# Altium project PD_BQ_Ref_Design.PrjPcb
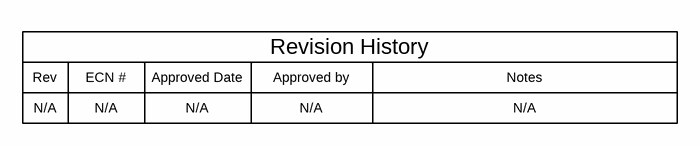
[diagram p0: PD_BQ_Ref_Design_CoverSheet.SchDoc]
TID: N/A; TechSupport: http://www.ti.com/support; SCH_Rev: A1; PRJ_Title: PD Reference Design; PRJ_Number: BMS046_; PRJ_Engineer: Hari Patel; PRJ_Customer: Public Release; PCB_Rev: A1; PCB_Layout: Outsource; CopyrightYear: 2018
7 sheets, 125 parts. Net scope: global (net labels, ports and power ports of the same name join across sheets).
Board file: PD_BQ_Ref_Design_PCB.PcbDoc
Sheets:
  PD_BQ_Ref_Design_BlankSheet.SchDoc
  PD_BQ_Ref_Design_CoverSheet.SchDoc
  PD_BQ_Ref_Design_Hardware.SchDoc
  TPS25750D.SchDoc
  BQ25792.SchDoc
  Type_C_Port.SchDoc
  Power_5V_3.3V.SchDoc

## Sheet PD_BQ_Ref_Design_BlankSheet.SchDoc
size 431 x 279 mm; Date: Not shown in title block; ApprovedBy: Not shown in title block; CheckedBy: Not shown in title block; Author: Not shown in title block; CompanyName: Not shown in title block; Engineer: Not shown in title block; Organization: Not shown in title block; Address1: Not shown in title block; Address2: Not shown in title block; Address3: Not shown in title block; Address4: Not shown in title block; DocumentNumber: 2; Revision: Use project parameter SCH_Rev; SheetNumber: 2; SheetTotal: 3; PageSetup: Record=PageOptions¦CenterHorizontal=True¦CenterVertical=True¦PrintScale=1.00¦XCorrection=1.00¦YCorrection=1.00¦PrintKind=0¦BorderSize=5000000¦LeftOffset=0¦BottomOffset=0¦Orientation=2¦PaperLength=1000¦PaperWidth=1000¦Scale=100¦PaperSource=15¦PrintQuality=600¦MediaType=1¦DitherType=10¦PaperKind=Letter¦PrintScaleMode=1

## Sheet PD_BQ_Ref_Design_CoverSheet.SchDoc
size 431 x 279 mm; Date: Not shown in title block; ApprovedBy: Not shown in title block; CheckedBy: Not shown in title block; Author: Not shown in title block; CompanyName: Not shown in title block; Engineer: Not shown in title block; Organization: Not shown in title block; Address1: Not shown in title block; Address2: Not shown in title block; Address3: Not shown in title block; Address4: Not shown in title block; DocumentNumber: 1; Revision: Use project parameter SCH_Rev; SheetNumber: 1; SheetTotal: 3; PageSetup: Record=PageOptions¦CenterHorizontal=True¦CenterVertical=True¦PrintScale=1.00¦XCorrection=1.00¦YCorrection=1.00¦PrintKind=0¦BorderSize=5000000¦LeftOffset=0¦BottomOffset=0¦Orientation=2¦PaperLength=1000¦PaperWidth=1000¦Scale=100¦PaperSource=15¦PrintQuality=600¦MediaType=1¦DitherType=10¦PaperKind=Letter¦PrintScaleMode=1

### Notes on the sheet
- Rev
- N/A
- ECN #
- Approved Date
- Approved by
- Revision History
- Notes

## Sheet PD_BQ_Ref_Design_Hardware.SchDoc
size 431 x 279 mm; Date: Not shown in title block; ApprovedBy: Not shown in title block; CheckedBy: Not shown in title block; Author: Not shown in title block; CompanyName: Not shown in title block; Engineer: Not shown in title block; Organization: Not shown in title block; Address1: Not shown in title block; Address2: Not shown in title block; Address3: Not shown in title block; Address4: Not shown in title block; DocumentNumber: 1; Revision: Use project parameter SCH_Rev; SheetNumber: 1; SheetTotal: 1; PageSetup: Record=PageOptions¦CenterHorizontal=True¦CenterVertical=True¦PrintScale=1.00¦XCorrection=1.00¦YCorrection=1.00¦PrintKind=0¦BorderSize=5000000¦LeftOffset=0¦BottomOffset=0¦Orientation=2¦PaperLength=1000¦PaperWidth=1000¦Scale=100¦PaperSource=15¦PrintQuality=600¦MediaType=1¦DitherType=10¦PaperKind=Letter¦PrintScaleMode=1
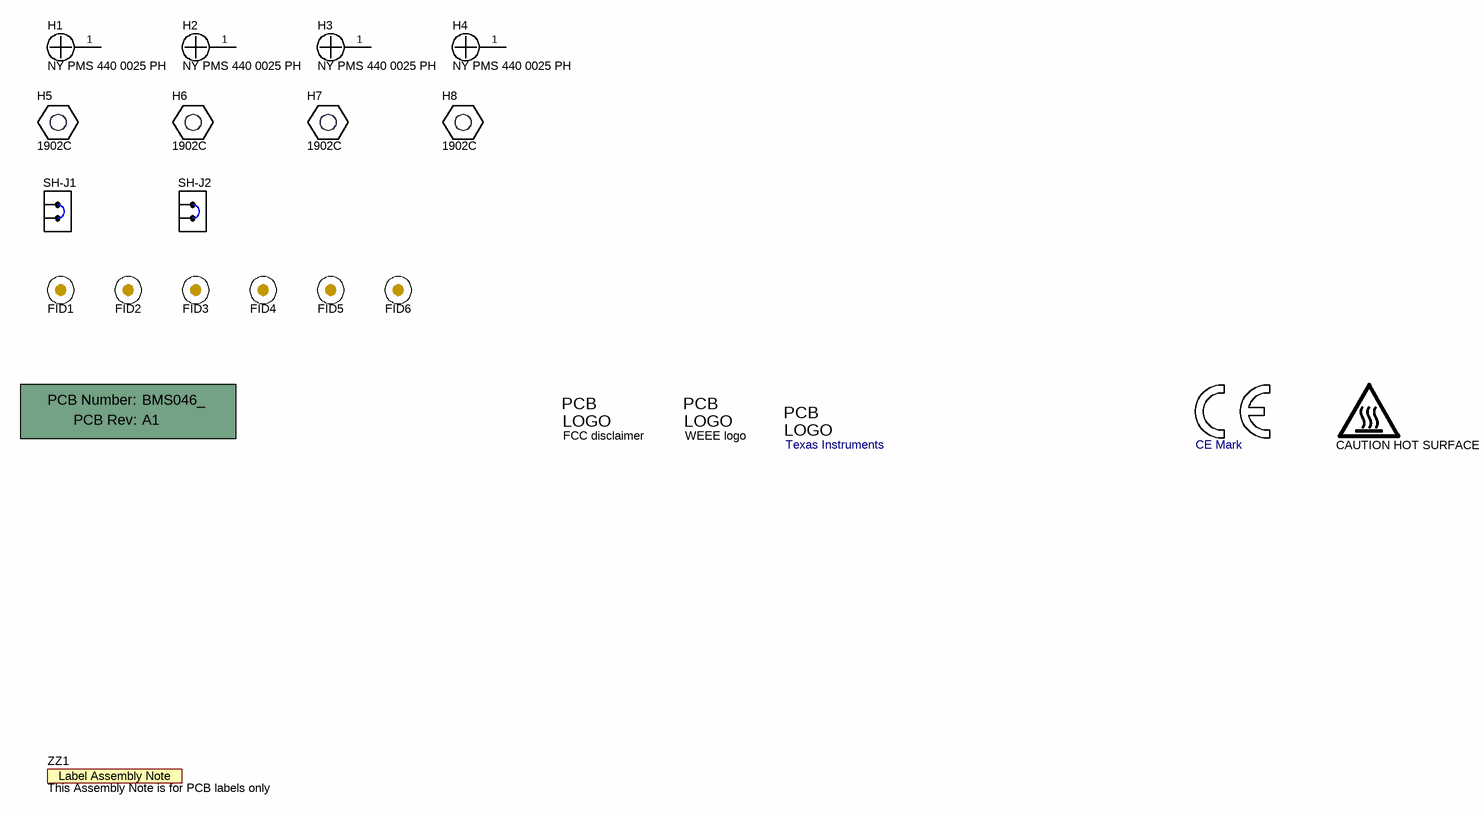
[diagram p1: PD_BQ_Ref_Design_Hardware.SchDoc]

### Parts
!PCB1  Printed Circuit Board  (value not drawn)  (mechanical)
FID1  Fiducial  [Fiducial10-20]  (value not drawn)
FID2  Fiducial  [Fiducial10-20]  (value not drawn)
FID3  Fiducial  [Fiducial10-20]  (value not drawn)
FID4  Fiducial  [Fiducial10-20]  (value not drawn)
FID5  Fiducial  [Fiducial10-20]  (value not drawn)
FID6  Fiducial  [Fiducial10-20]  (value not drawn)
H1  NY PMS 440 0025 PH  [NY PMS 440 0025 PH]
H2  NY PMS 440 0025 PH  [NY PMS 440 0025 PH]
H3  NY PMS 440 0025 PH  [NY PMS 440 0025 PH]
H4  NY PMS 440 0025 PH  [NY PMS 440 0025 PH]
H5  1902C  [Keystone_1902C]
H6  1902C  [Keystone_1902C]
H7  1902C  [Keystone_1902C]
H8  1902C  [Keystone_1902C]
Logo1  CE Mark  [CE_Mark_5mm]  (no BOM)
Logo2  Texas Instruments  [TI_Horizontal_Overlay_Small]  (no BOM)
Logo3  FCC disclaimer  [FCC_disclaimer]  (no BOM)
Logo4  WEEE logo  [WEEE_Minimum]  (no BOM)
LOGO5  CAUTION HOT SURFACE  [IEC_HotSurface_Small]  (no BOM)
SH-J1  SNT-100-BK-G  [SNT-100-BK-G]  (value not drawn)
SH-J2  SNT-100-BK-G  [SNT-100-BK-G]  (value not drawn)
ZZ1  This Assembly Note is for PCB labels only  [AssemblyNoteLabel]  (no BOM)

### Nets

Not connected (* = marked no-connect by the designer): H1 1; H2 1; H3 1; H4 1

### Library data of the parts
!PCB1 = CMP-0003618-2: Manufacturer: Any; PartNumber: BMS046_
FID1-FID6 = CMP-0077181-1: Fiducial mark.  There is nothing to buy or mount.
H1-H4 = CMP-0003617-1: Machine Screw, Round, #4-40 x 1/4, Nylon, Philips panhead; Manufacturer: B&F Fastener Supply; CompType: Hardware
H5-H8 = CMP-0003610-1: Standoff, Hex, 0.5"L #4-40 Nylon; Manufacturer: Keystone; CompType: Hardware
Logo1 = CMP-0074844-1: SymbolCreator: a0412235
Logo2 = CMP-0074838-1: Texas Instrument Corporate Signature; SymbolCreator: a0412235; Lib Reference: TI_Logo
Logo3 = CMP-0074847-1: FCC_disclaimer; Library Reference: Logo
Logo4 = CMP-0074769-1
LOGO5 = CMP-0074837-1: IEC 61010-1 Hot Surface Warning; SymbolCreator: a0412235
SH-J1 SH-J2 = CMP-0003623-1: Shunt, 100mil, Gold plated, Black; Alternate PartNumber: 969102-0000-DA; Manufacturer: Samtec; Alternate Manufacturer: 3M; Value: 1x2; Note: You can "mate" this to a header by matching the designator.  i.e. use SH-J3 for header J3
ZZ1 = CMP-0003616-3

## Sheet TPS25750D.SchDoc
size A2; Date: Not shown in title block; ApprovedBy: Not shown in title block; CheckedBy: Not shown in title block; Author: Not shown in title block; CompanyName: Not shown in title block; Engineer: Not shown in title block; Organization: Not shown in title block; Address1: Not shown in title block; Address2: Not shown in title block; Address3: Not shown in title block; Address4: Not shown in title block; DocumentNumber: 2; Revision: Use project parameter SCH_Rev; SheetNumber: 2; SheetTotal: 3; PageSetup: Record=PageOptions¦CenterHorizontal=True¦CenterVertical=True¦PrintScale=1.00¦XCorrection=1.00¦YCorrection=1.00¦PrintKind=0¦BorderSize=5000000¦LeftOffset=0¦BottomOffset=0¦Orientation=2¦PaperLength=1000¦PaperWidth=1000¦Scale=100¦PaperSource=15¦PrintQuality=600¦MediaType=1¦DitherType=10¦PaperKind=Letter¦PrintScaleMode=1
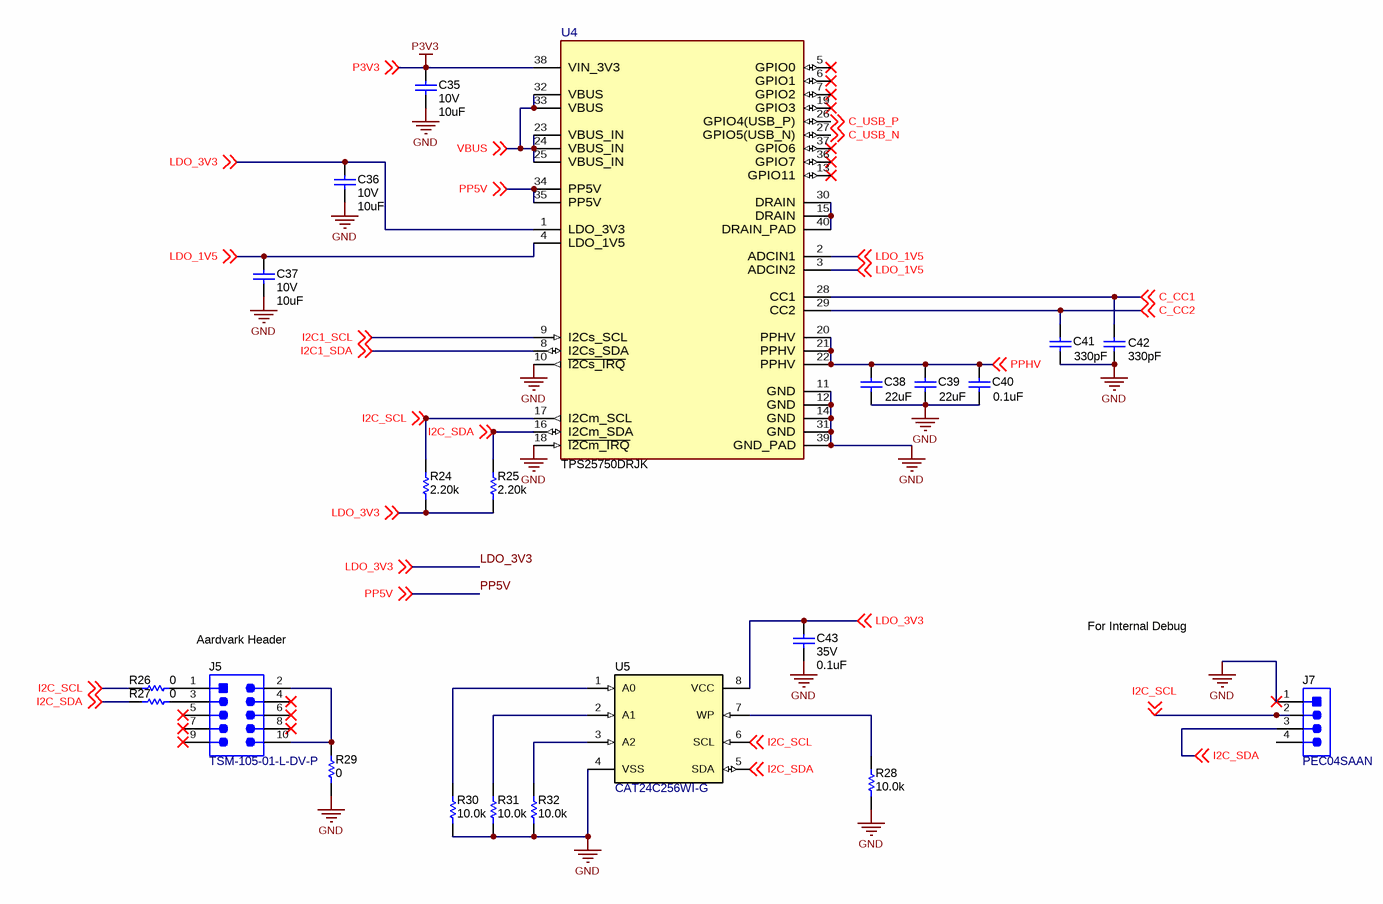
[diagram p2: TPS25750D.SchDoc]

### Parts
C35  VDC_V: 10V  ValueDisplayed: 10uF  [0402_070]  (hidden comment: CL05A106MP5NUNC)
C36  VDC_V: 10V  ValueDisplayed: 10uF  [0402_070]  (hidden comment: CL05A106MP5NUNC)
C37  VDC_V: 10V  ValueDisplayed: 10uF  [0402_070]  (hidden comment: CL05A106MP5NUNC)
C38  ValueDisplayed: 22uF  [0805_HV]  (hidden comment: C2012X5R1V226M125AC)
C39  ValueDisplayed: 22uF  [0805_HV]  (hidden comment: C2012X5R1V226M125AC)
C40  ValueDisplayed: 0.1uF  [0402]  (hidden comment: GMK105BJ104KV-F)
C41  ValueDisplayed: 330pF  [0201_033]  (hidden comment: GRM033R71H331KA12D)
C42  ValueDisplayed: 330pF  [0201_033]  (hidden comment: GRM033R71H331KA12D)
C43  VDC_V: 35V  ValueDisplayed: 0.1uF  [0402]  (hidden comment: GMK105BJ104KV-F)
J5  TSM-105-01-L-DV-P  [Samtec_TSM-105-01-x-DV]
J7  PEC04SAAN  [SULLINS_PEC04SAAN]
R24  ValueDisplayed: 2.20k  [0201]  (hidden comment: CRCW02012K20FKED)
R25  ValueDisplayed: 2.20k  [0201]  (hidden comment: CRCW02012K20FKED)
R26  ValueDisplayed: 0  [0201]  (hidden comment: CRCW02010000Z0ED)
R27  ValueDisplayed: 0  [0201]  (hidden comment: CRCW02010000Z0ED)
R28  ValueDisplayed: 10.0k  [0201]  (hidden comment: CRCW020110K0FKED)
R29  ValueDisplayed: 0  [0201]  (hidden comment: CRCW02010000Z0ED)
R30  ValueDisplayed: 10.0k  [0201]  (hidden comment: CRCW020110K0FKED)
R31  ValueDisplayed: 10.0k  [0201]  (hidden comment: CRCW020110K0FKED)
R32  ValueDisplayed: 10.0k  [0201]  (hidden comment: CRCW020110K0FKED)
U4  TPS25750DRJK  [RJK0038B-C01-MFG]
U5  CAT24C256WI-G  [SOIC-8]

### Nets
GND: C35.2 C36.2 C37.2 C38.2 C39.2 C40.2 C41.2 C42.2 C43.2 J7.1 R28.1 R29.1 R30.1 R31.1 R32.1 U4.10(~{I2Cs_IRQ}) U4.11(GND) U4.12(GND) U4.14(GND) U4.18(~{I2Cm_IRQ}) U4.31(GND) U4.39(GND_PAD) U5.4(VSS)
P3V3: C35.1 U4.38(VIN_3V3) ; off-sheet P3V3
C_CC1: C42.1 U4.28(CC1) ; off-sheet C_CC1
C_CC2: C41.1 U4.29(CC2) ; off-sheet C_CC2
C_USB_N: U4.27(GPIO5(USB_N)) ; off-sheet C_USB_N
C_USB_P: U4.26(GPIO4(USB_P)) ; off-sheet C_USB_P
I2C1_SCL: U4.9(I2Cs_SCL) ; off-sheet I2C1_SCL
I2C1_SDA: U4.8(I2Cs_SDA) ; off-sheet I2C1_SDA
I2C_SCL: J7.2 R24.2 R26.1 U4.17(I2Cm_SCL) U5.6(SCL) ; off-sheet I2C_SCL
I2C_SDA: J7.3 R25.2 R27.1 U4.16(I2Cm_SDA) U5.5(SDA) ; off-sheet I2C_SDA
LDO_1V5: C37.1 U4.2(ADCIN1) U4.3(ADCIN2) U4.4(LDO_1V5) ; off-sheet LDO_1V5
LDO_3V3: C36.1 C43.1 R24.1 R25.1 U4.1(LDO_3V3) U5.8(VCC) ; off-sheet LDO_3V3
PP5V: U4.34(PP5V) U4.35(PP5V) ; off-sheet PP5V
PPHV: C38.1 C39.1 C40.1 U4.20(PPHV) U4.21(PPHV) U4.22(PPHV) ; off-sheet PPHV
VBUS: U4.23(VBUS_IN) U4.24(VBUS_IN) U4.25(VBUS_IN) U4.32(VBUS) U4.33(VBUS) ; off-sheet VBUS
NetJ5_1: J5.1 R26.2
NetJ5_2: J5.2 J5.10 R29.2
NetJ5_3: J5.3 R27.2
NetR28_2: R28.2 U5.7(WP)
NetR30_2: R30.2 U5.1(A0)
NetR31_2: R31.2 U5.2(A1)
NetR32_2: R32.2 U5.3(A2)
NetU4_15: U4.15(DRAIN) U4.30(DRAIN) U4.40(DRAIN_PAD)

Not connected (* = marked no-connect by the designer): J5 4* 5* 6* 7* 8* 9*; J7 4; U4 5(GPIO0)* 6(GPIO1)* 7(GPIO2)* 13(GPIO11)* 19(GPIO3)* 36(GPIO7)* 37(GPIO6)*

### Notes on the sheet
- Aardvark Header
- For Internal Debug

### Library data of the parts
C35-C37 = CMP-0006339-4: CAP, CERM, 10 uF, 10 V, +/- 20%, X5R, 0402; Manufacturer: Samsung Electro-Mechanics; TaMin_C: -55°C; Polarized: N; SizeAreaWB_mm2: 3; Value1: Unknown; U/M: EA; Value: 10uF; TaMax_C: 85°C; SizeZ_mm: 0.6; SizeX_mm: 1; SizeY_mm: 0.5; Cap_Case: 0402; Cap_F: 10µF; AEC Category: Q200
C38 C39 = CMP-0007844-2: CAP, CERM, 22 uF, 35 V, +/- 20%, X5R, 0805; Manufacturer: TDK; TaMin_C: -55°C; ESR_ohm: 2.05m; Polarized: N; SizeAreaWB_mm2: 6.75; Value1: 0.00205 ohm; U/M: EA; Value: 22uF; TaMax_C: 85°C; SizeZ_mm: 1.45; SizeX_mm: 2; SizeY_mm: 1.25; Cap_Case: 0805; Value2: 35V; SizeArea_mm2: 2.5; Cap_F: 22µF; IRMS_A: 4.55587A; AEC Category: Q200
C40 = CMP-0006370-2: CAP, CERM, 0.1 uF, 35 V, +/- 10%, X5R, 0402; Manufacturer: Taiyo Yuden; TaMin_C: -55°C; Polarized: N; SizeAreaWB_mm2: 3; Value1: Unknown; U/M: EA; Value: 0.1uF; TaMax_C: 85°C; SizeZ_mm: 0.6; SizeX_mm: 1; SizeY_mm: 0.5; Value2: 35V; Cap_F: 100nF; AEC Category: Q200
C41 C42 = CMP-0009779-2: CAP, CERM, 330 pF, 50 V, +/- 10%, X7R, 0201; Manufacturer: MuRata; TaMin_C: -55°C; Polarized: N; SizeAreaWB_mm2: 2.08; Value1: Unknown; U/M: EA; Value: 330pF; TaMax_C: 125°C; SizeZ_mm: 0.33; SizeX_mm: 0.6; SizeY_mm: 0.3; Cap_Case: 0201; Value2: 50V; SizeArea_mm2: 0.18; AEC Category: Q200
C43 = CMP-0006370-2: CAP, CERM, 0.1 uF, 35 V, +/- 10%, X5R, 0402; Manufacturer: Taiyo Yuden; TaMin_C: -55°C; Polarized: N; SizeAreaWB_mm2: 3; Value1: Unknown; U/M: EA; Value: 0.1uF; TaMax_C: 85°C; SizeZ_mm: 0.6; SizeX_mm: 1; SizeY_mm: 0.5; Cap_F: 100nF; AEC Category: Q200
J5 = CMP-0055598-2: Header, 2.54mm, 5x2, Gold, SMT; Manufacturer: Samtec; Current_A: 5.4A; Green_Lifecycle: Active; Shrouded: N; Gender: Male; Cert_CSA: Y; Green_REACh: Passed; Voltage_V: 475V; Row_Count: 2; RowSpacing_mm: 2.54
J7 = CMP-0054562-1: Header, 100mil, 4x1, Tin, TH; Manufacturer: Sullins Connector Solutions; CNHeader: TRUE; Current_A: 3A; Green_Lifecycle: Not Set; Shrouded: N; Gender: Male; Green_REACh: Incomplete; Voltage_V: 1.8kV; Row_Count: 1; Pitch_mm: 2.54; CT: FALSE; Cert_UL: Y
R24 R25 = CMP-0027272-3: RES, 2.20 k, 1%, 0.05 W, 0201; Manufacturer: Vishay-Dale; Power_W: 50mW; TempCo: 100 ppm/C; Value_Code: 2k20; Value: 2.20k; Res_ohm: 2.2k; SizeX_mm: 0.6; SizeY_mm: 0.3; SizeZ_mm: 0.26; Value2: 0.05W; SizeArea_mm2: 0.18; AEC Qualified: N; VDC_V: 30V; AEC Category: Q200
R26 R27 R29 = CMP-0027008-4: RES, 0, 5%, 0.05 W, 0201; Manufacturer: Vishay-Dale; Power_W: 50mW; TempCo: ppm/C; Value_Code: 0000; Value: 0; EIA_Code: E24; SizeX_mm: 0.6; SizeY_mm: 0.3; SizeZ_mm: 0.26; Value2: 0.05W; SizeArea_mm2: 0.18; AEC Qualified: N; AEC Category: Q200
R28 R30-R32 = CMP-0027262-3: RES, 10.0 k, 1%, 0.05 W, 0201; Manufacturer: Vishay-Dale; Power_W: 50mW; TempCo: 100 ppm/C; Value_Code: 10k0; Value: 10.0k; EIA_Code: E96; Res_ohm: 10k; SizeX_mm: 0.6; SizeY_mm: 0.3; SizeZ_mm: 0.26; Value2: 0.05W; SizeArea_mm2: 0.18; AEC Qualified: N; VDC_V: 30V; AEC Category: Q200
U4 = CMP-0090338-5: USB Type-C and USB PD Controller with Integrated Power Switches Optimized for Power Applications; Manufacturer: Texas Instruments; CompType: IC; Usb Standard: USB 3.0; AEC Category: Q200; SizeZ_mm: 0.8mm; Standoff Height: 0mm; AEC Qualified: No; Max Supply Voltage: 22V; TaMax_C: +105°C; Min Supply Voltage: 3V; TaMin_C: -40°C; TJmax_C: +175°C; Number Of Ports: 1
U5 = CMP-0005314-2: 256 kb I2C CMOS Serial EEPROM, SOIC-8; Manufacturer: ON Semiconductor; SizeAreaWB_mm2: 55.131; SizeZ_mm: 1.75; SizeX_mm: 5.99; SizeY_mm: 4.9; SizeArea_mm2: 29.351

## Sheet BQ25792.SchDoc
size A2; Date: Not shown in title block; ApprovedBy: Not shown in title block; CheckedBy: Not shown in title block; Author: Not shown in title block; CompanyName: Not shown in title block; Engineer: Not shown in title block; Organization: Not shown in title block; Address1: Not shown in title block; Address2: Not shown in title block; Address3: Not shown in title block; Address4: Not shown in title block; DocumentNumber: 2; Revision: Use project parameter SCH_Rev; SheetNumber: 2; SheetTotal: 3; PageSetup: Record=PageOptions¦CenterHorizontal=True¦CenterVertical=True¦PrintScale=1.00¦XCorrection=1.00¦YCorrection=1.00¦PrintKind=0¦BorderSize=5000000¦LeftOffset=0¦BottomOffset=0¦Orientation=2¦PaperLength=1000¦PaperWidth=1000¦Scale=100¦PaperSource=15¦PrintQuality=600¦MediaType=1¦DitherType=10¦PaperKind=Letter¦PrintScaleMode=1
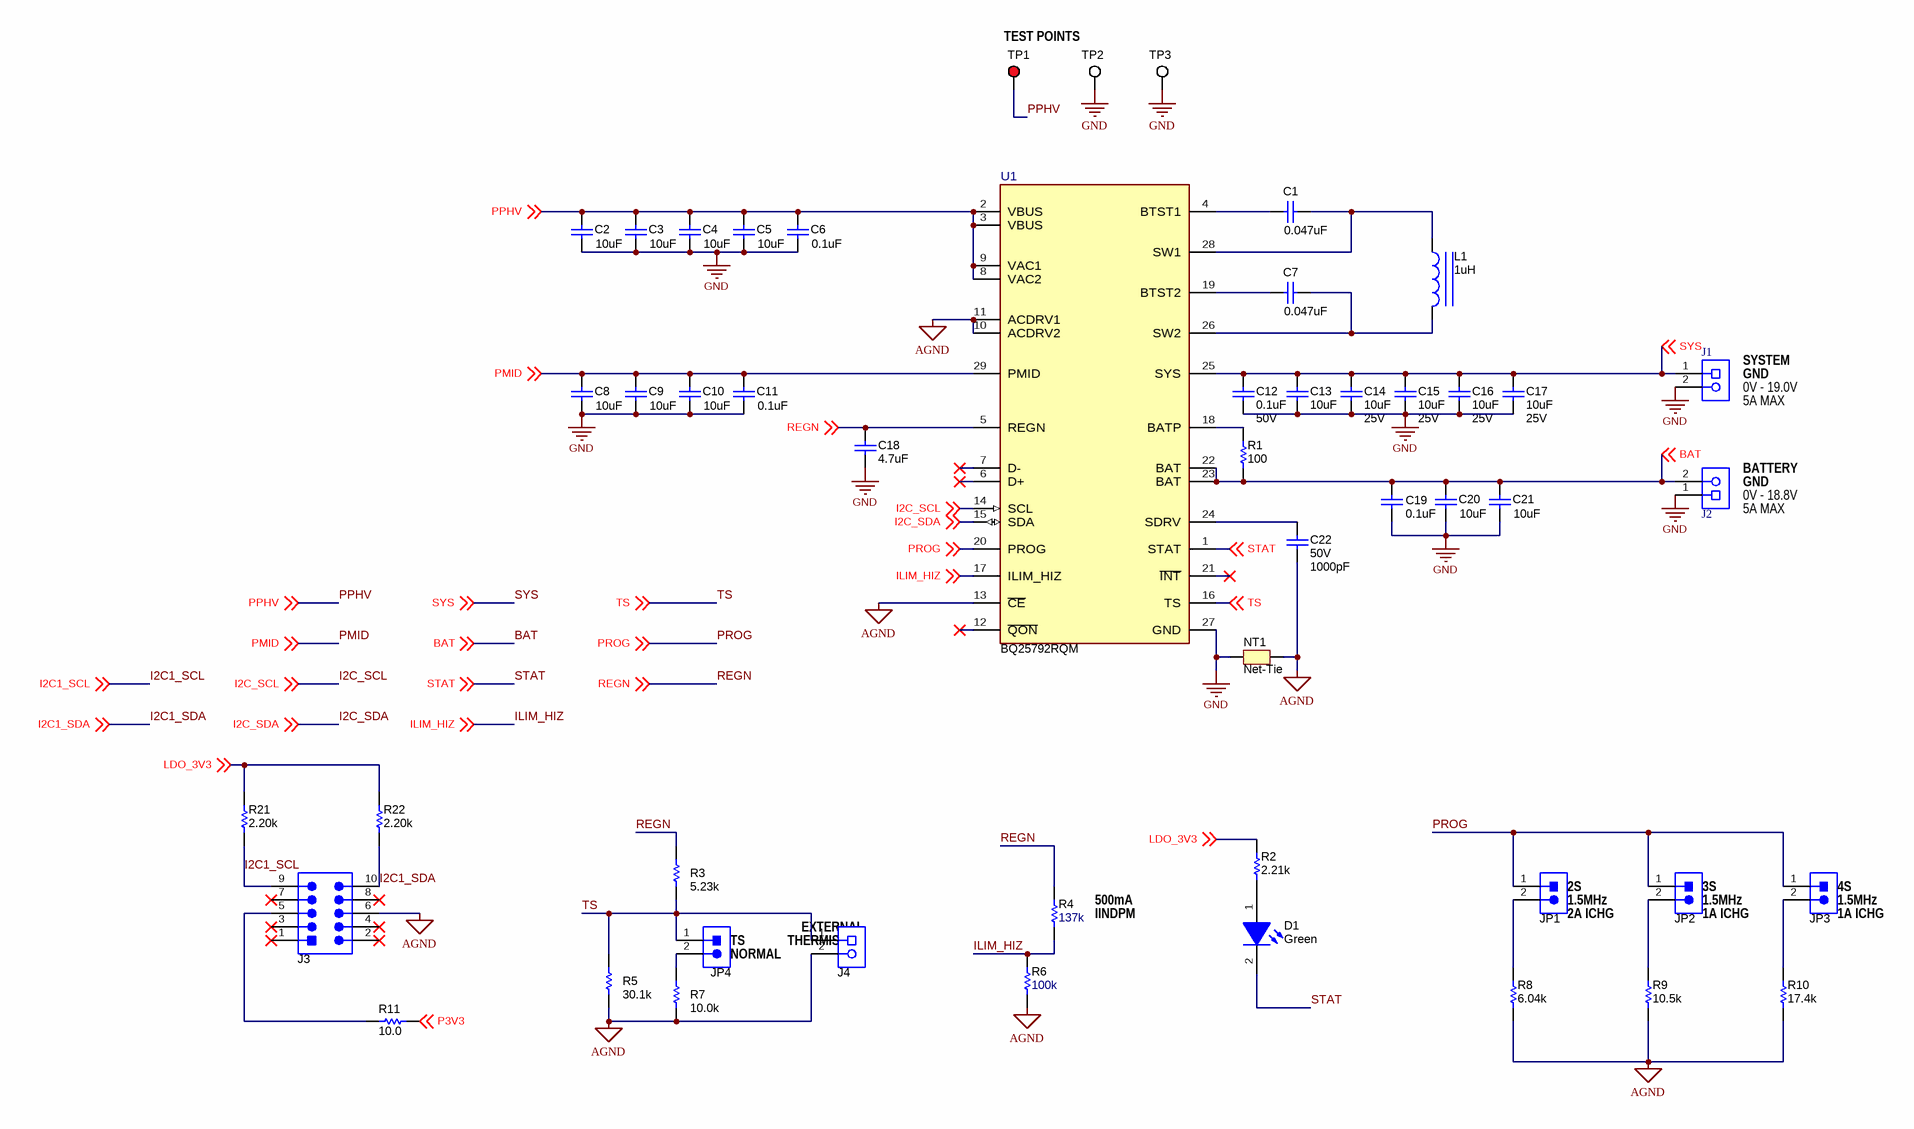
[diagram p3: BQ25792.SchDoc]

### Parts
C1  ValueDisplayed: 0.047uF  [0402]  (hidden comment: GRM155R71E473KA88D)
C2  ValueDisplayed: 10uF  [0603]  (hidden comment: GRT188R61E106ME13D)
C3  ValueDisplayed: 10uF  [0603]  (hidden comment: GRT188R61E106ME13D)
C4  ValueDisplayed: 10uF  [0603]  (hidden comment: GRT188R61E106ME13D)
C5  ValueDisplayed: 10uF  [0603]  (hidden comment: GRT188R61E106ME13D)
C6  ValueDisplayed: 0.1uF  [0402]  (hidden comment: C1005X7R1H104K050BE)
C7  ValueDisplayed: 0.047uF  [0402]  (hidden comment: GRM155R71E473KA88D)
C8  ValueDisplayed: 10uF  [0603]  (hidden comment: GRT188R61E106ME13D)
C9  ValueDisplayed: 10uF  [0603]  (hidden comment: GRT188R61E106ME13D)
C10  ValueDisplayed: 10uF  [0603]  (hidden comment: GRT188R61E106ME13D)
C11  ValueDisplayed: 0.1uF  [0402]  (hidden comment: C1005X7R1H104K050BE)
C12  ValueDisplayed: 0.1uF  VDC_V: 50V  [0402]  (hidden comment: C1005X7R1H104K050BE)
C13  ValueDisplayed: 10uF  [0805_HV]  (hidden comment: C2012X5R1E106K125AB)
C14  ValueDisplayed: 10uF  VDC_V: 25V  [0805_HV]  (hidden comment: C2012X5R1E106K125AB)
C15  ValueDisplayed: 10uF  VDC_V: 25V  [0805_HV]  (hidden comment: C2012X5R1E106K125AB)
C16  ValueDisplayed: 10uF  VDC_V: 25V  [0805_HV]  (hidden comment: C2012X5R1E106K125AB)
C17  ValueDisplayed: 10uF  VDC_V: 25V  [0805_HV]  (hidden comment: C2012X5R1E106K125AB)
C18  ValueDisplayed: 4.7uF  [0603]  (hidden comment: GRM188R61C475KAAJ)
C19  ValueDisplayed: 0.1uF  [0402L]  (hidden comment: C1005X7R1H104K050BE)
C20  ValueDisplayed: 10uF  [0603]  (hidden comment: GRT188R61E106ME13D)
C21  ValueDisplayed: 10uF  [0603]  (hidden comment: GRT188R61E106ME13D)
C22  VDC_V: 50V  ValueDisplayed: 1000pF  [0402]  (hidden comment: C0402C102K5RACTU)
D1  value Green  [LED_LTST-C190]  (hidden comment: LTST-C190GKT)
J1  ED120/2DS  [On-Shore_ED120_2DS]  (value not drawn)
J2  ED120/2DS  [On-Shore_ED120_2DS]  (value not drawn)
J3  N2510-6002-RB  [CONN_2510-6002]  (value not drawn)
J4  0393570002  [MOLEX_39357-0002]  (value not drawn)
JP1  Header_2x1  [CONN_PEC02SAAN]  (value not drawn)
JP2  Header_2x1  [CONN_PEC02SAAN]  (value not drawn)
JP3  Header_2x1  [CONN_PEC02SAAN]  (value not drawn)
JP4  Header_2x1  [CONN_PEC02SAAN]  (value not drawn)
L1  ValueDisplayed: 1uH  [IHLP-2020BZ]  (hidden comment: IHLP2020BZER1R0M11)
NT1  Net-Tie  [Net-Tie_20milWide_60milLong]  (net tie, no BOM)
R1  ValueDisplayed: 100  [0603]  (hidden comment: RC0603FR-07100RL)
R2  value 2.21k  [0402]  (hidden comment: CRCW04022K21FKED)
R3  value 5.23k  [0402]  (hidden comment: Resistor)
R4  ValueDisplayed: 137k  [0603]  (hidden comment: RC0603FR-07137KL)
R5  value 30.1k  [0402]  (hidden comment: Resistor)
R6  ValueDisplayed: 100k  [0603]  (hidden comment: RC0603FR-07100KL)
R7  value 10.0k  [0402]  (hidden comment: Resistor)
R8  ValueDisplayed: 6.04k  [0603]  (hidden comment: RC0603FR-076K04L)
R9  ValueDisplayed: 10.5k  [0603]  (hidden comment: CRCW060310K5FKEA)
R10  ValueDisplayed: 17.4k  [0603]  (hidden comment: CRCW060317K4FKEA)
R11  ValueDisplayed: 10.0  [1206]  (hidden comment: ERJ-8ENF10R0V)
R21  ValueDisplayed: 2.20k  [0201]  (hidden comment: CRCW02012K20FKED)
R22  ValueDisplayed: 2.20k  [0201]  (hidden comment: CRCW02012K20FKED)
TP1  5000  [Keystone5000]  (value not drawn)
TP2  5016  [Testpoint_Keystone_Compact]  (value not drawn)
TP3  5016  [Testpoint_Keystone_Compact]  (value not drawn)
U1  BQ25792RQM  [RQM0029A-MFG]

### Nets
AGND: C22.2 J3.6 J4.2 NT1.2 R5.1 R6.1 R7.1 R8.1 R9.1 R10.1 U1.10(ACDRV2) U1.11(ACDRV1) U1.13(~{CE})
GND: C2.1 C3.1 C4.1 C5.1 C6.2 C8.1 C9.1 C10.1 C11.2 C12.2 C13.2 C14.2 C15.2 C16.2 C17.2 C18.2 C19.2 C20.2 C21.2 J1.2 J2.1 NT1.1 TP2.1 TP3.1 U1.27(GND)
P3V3: R11.2 ; off-sheet P3V3
BAT: C19.1 C20.1 C21.1 J2.2 R1.1 U1.22(BAT) U1.23(BAT) ; off-sheet BAT
I2C1_SCL: J3.9 R21.1 ; off-sheet I2C1_SCL
I2C1_SDA: J3.10 R22.1 ; off-sheet I2C1_SDA
I2C_SCL: U1.14(SCL) ; off-sheet I2C_SCL
I2C_SDA: U1.15(SDA) ; off-sheet I2C_SDA
ILIM_HIZ: R4.1 R6.2 U1.17(ILIM_HIZ) ; off-sheet ILIM_HIZ
LDO_3V3: R2.2 R21.2 R22.2 ; off-sheet LDO_3V3
PMID: C8.2 C9.2 C10.2 C11.1 U1.29(PMID) ; off-sheet PMID
PPHV: C2.2 C3.2 C4.2 C5.2 C6.1 TP1.1 U1.2(VBUS) U1.3(VBUS) U1.8(VAC2) U1.9(VAC1) ; off-sheet PPHV
PROG: JP1.1 JP2.1 JP3.1 U1.20(PROG) ; off-sheet PROG
REGN: C18.1 R3.2 R4.2 U1.5(REGN) ; off-sheet REGN
STAT: D1.2(K) U1.1(STAT) ; off-sheet STAT
SYS: C12.1 C13.1 C14.1 C15.1 C16.1 C17.1 J1.1 U1.25(SYS) ; off-sheet SYS
TS: J4.1 JP4.1 R3.1 R5.2 U1.16(TS) ; off-sheet TS
NetC1_1: C1.1 U1.4(BTST1)
NetC1_2: C1.2 L1.1 U1.28(SW1)
NetC7_1: C7.1 U1.19(BTST2)
NetC7_2: C7.2 L1.2 U1.26(SW2)
NetC22_1: C22.1 U1.24(SDRV)
NetD1_1: D1.1(A) R2.1
NetJ3_5: J3.5 R11.1
NetJP1_2: JP1.2 R8.2
NetJP2_2: JP2.2 R9.2
NetJP3_2: JP3.2 R10.2
NetJP4_2: JP4.2 R7.2
NetR1_2: R1.2 U1.18(BATP)

Not connected (* = marked no-connect by the designer): J3 1* 2* 3* 4* 7* 8*; U1 6(D+)* 7(D-)* 12(~{QON})* 21(~{INT})*

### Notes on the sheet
- TEST POINTS
- (near J1) GND
- (near J1) 0V - 19.0V
- (near J1) 5A MAX
- (near J1) SYSTEM
- (near J2) BATTERY
- (near J2) GND
- (near J2) 0V - 18.8V
- (near J2) 5A MAX
- (near JP4) TS
- (near J4) EXTERNAL
- (near J4) THERMISTOR
- (near R4) 500mA
- (near R4) IINDPM
- (near JP1) 2S
- (near JP1) 1.5MHz
- (near JP1) 2A ICHG
- (near JP2) 3S
- (near JP2) 1.5MHz
- (near JP2) 1A ICHG
- (near JP3) 4S
- (near JP3) 1.5MHz
- (near JP3) 1A ICHG
- (near JP4) NORMAL
- (near J4) GND

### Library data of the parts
C1 C7 = CMP-0006669-2: CAP, CERM, 0.047 uF, 25 V, +/- 10%, X7R, 0402; Manufacturer: MuRata; TaMin_C: -55°C; Polarized: N; SizeAreaWB_mm2: 3; Value1: Unknown; U/M: EA; TaMax_C: 125°C; SizeZ_mm: 0.6; SizeX_mm: 1; SizeY_mm: 0.5; Value2: 25V; Cap_F: 47nF; AEC Category: Q200
C2-C5 C8-C10 C20 C21 = CMP-0007501-5: CAP, CERM, 10 uF, 25 V, +/- 20%, X5R, 0603; Manufacturer: MuRata; TaMin_C: -55°C; Polarized: N; SizeAreaWB_mm2: 4.68; Value1: Unknown; U/M: EA; Value: 10uF; TaMax_C: 85°C; SizeZ_mm: 1; SizeX_mm: 1.6; SizeY_mm: 0.8; Value2: 25V; SizeArea_mm2: 1.28; Cap_F: 10µF; AEC Category: Q200
C6 C11 = CMP-0064946-2: CAP, CERM, 0.1 uF, 50 V,+/- 10%, X7R, 0402; Manufacturer: TDK; TaMin_C: -55°C; Polarized: N; SizeAreaWB_mm2: 3; Value1: Unknown; U/M: EA; Value: 0.1uF; TaMax_C: 125°C; SizeZ_mm: 0.6; SizeX_mm: 1; SizeY_mm: 0.5; Value2: 50V; Cap_F: 100nF; AEC Category: Q200
C12 = CMP-0064946-2: CAP, CERM, 0.1 uF, 50 V,+/- 10%, X7R, 0402; Manufacturer: TDK; TaMin_C: -55°C; Polarized: N; SizeAreaWB_mm2: 3; Value1: Unknown; U/M: EA; Value: 0.1uF; TaMax_C: 125°C; SizeZ_mm: 0.6; SizeX_mm: 1; SizeY_mm: 0.5; Cap_F: 100nF; AEC Category: Q200
C13 = CMP-0007828-2: CAP, CERM, 10 uF, 25 V, +/- 10%, X5R, 0805; Manufacturer: TDK; TaMin_C: -55°C; Polarized: N; SizeAreaWB_mm2: 6.75; Value1: Unknown; U/M: EA; Value: 10uF; TaMax_C: 85°C; SizeZ_mm: 1.45; SizeX_mm: 2; SizeY_mm: 1.25; Cap_Case: 0805; Value2: 25V; SizeArea_mm2: 2.5; Cap_F: 10µF; AEC Category: Q200
C14-C17 = CMP-0007828-2: CAP, CERM, 10 uF, 25 V, +/- 10%, X5R, 0805; Manufacturer: TDK; TaMin_C: -55°C; Polarized: N; SizeAreaWB_mm2: 6.75; Value1: Unknown; U/M: EA; Value: 10uF; TaMax_C: 85°C; SizeZ_mm: 1.45; SizeX_mm: 2; SizeY_mm: 1.25; Cap_Case: 0805; SizeArea_mm2: 2.5; Cap_F: 10µF; AEC Category: Q200
C18 = CMP-0007341-5: CAP, CERM, 4.7 uF, 16 V, +/- 10%, X5R, 0603; Manufacturer: MuRata; TaMin_C: -55°C; Polarized: N; SizeAreaWB_mm2: 4.68; Value1: Unknown; U/M: EA; Value: 4.7uF; TaMax_C: 85°C; SizeZ_mm: 1; SizeX_mm: 1.6; SizeY_mm: 0.8; Value2: 16V; SizeArea_mm2: 1.28; Cap_F: 4.7µF; AEC Category: Q200
C19 = CMP-0064946-2: CAP, CERM, 0.1 uF, 50 V,+/- 10%, X7R, 0402; Manufacturer: TDK; TaMin_C: -55°C; Polarized: N; SizeAreaWB_mm2: 3; Value1: Unknown; U/M: EA; Value: 0.1uF; TaMax_C: 125°C; SizeZ_mm: 0.6; SizeX_mm: 1; SizeY_mm: 0.5; Cap_Case: 0402; Value2: 50V; Cap_F: 100nF; AEC Category: Q200
C22 = CMP-0006235-2: CAP, CERM, 1000 pF, 50 V, +/- 10%, X7R, 0402; Manufacturer: Kemet; TaMin_C: -55°C; Polarized: N; SizeAreaWB_mm2: 3; Value1: Unknown; U/M: EA; Value: 1000pF; TaMax_C: 125°C; SizeZ_mm: 0.6; SizeX_mm: 1; SizeY_mm: 0.5; Cap_F: 1nF; AEC Category: Q200
D1 = CMP-0002827-3: LED, Green, SMD; Manufacturer: Lite-On; Vf_V: 2.1V; Io_A: 20mA; Power_TotalModule: 100mW; Value1: 0.1W
J1 J2 = CMP-0074910-1: Terminal Block, 5.08 mm, 2x1, Brass, TH; Manufacturer: On-Shore Technology; Cert_VDE: Y; CNHeader: False; Current_A: 15A; Green_Lifecycle: Not Set; Shrouded: N; Gender: Female; Green_REACh: Incomplete; Voltage_V: 300V; Row_Count: 1; Pitch_mm: 5.08; CT: True
J3 = CMP-0055448-2: Header (shrouded), 100mil, 5x2, High-Temperature, Gold, TH; Manufacturer: 3M; Green_Lifecycle: Active; Green_REACh: Passed
J4 = CMP-0055341-2: Terminal Block, 3.5 mm, 2x1, Tin, TH; Manufacturer: Molex; CNHeader: FALSE; CT: TRUE; Green_Lifecycle: Not Set; Green_REACh: Incomplete
JP1-JP4 = CMP-0002337-1: Header, 100mil, 2x1, Tin, TH; PartNumber: PEC02SAAN; Manufacturer: Sullins Connector Solutions; Pitch_mm: 2.54; Gender: Male; Shrouded: N; Row_Count: 1; Current_A: 3A; Voltage_V: 1.8kV; Cert_UL: Y; CNHeader: TRUE; CT: FALSE; Green_Lifecycle: Not Set; Green_REACh: Incomplete
L1 = CMP-0063290-1: Inductor, Shielded Drum Core, Powdered Iron, 1 uH, 7 A, 0.0181 ohm, SMD; Manufacturer: Vishay-Dale; Isat: 7A @ 20% inductance drop; Irms: 7.5A @ 40C rise; Green_Lifecycle: Active; SizeAreaWB_mm2: 53.7782; DCR_ohm: 0.0181; Green_REACh: Passed; Value: 1uH; Imax_A: 7A; SizeZ_mm: 2; SizeX_mm: 5.49; SizeY_mm: 5.18; SizeArea_mm2: 28.4382; Ind_H: 1µH; AEC Category: Q200
NT1 = CMP-0078142-3: Single point connection between nets.
R1 = CMP-0022736-4: RES, 100, 1%, 0.1 W, 0603; Manufacturer: Yageo; Power_W: 100mW; TempCo: 100 ppm/C; Value_Code: 100R; Value: 100; EIA_Code: E96; SizeX_mm: 1.6; SizeY_mm: 0.8; SizeZ_mm: 1; Value2: 0.1W; SizeArea_mm2: 1.28; AEC Qualified: N; VDC_V: 75V; AEC Category: Q200; SizeAreaWB_mm2: 4.68
R2 = CMP-0026232-2: RES, 2.21 k, 1%, 0.063 W, AEC-Q200 Grade 0, 0402; Manufacturer: Vishay-Dale; Value_Code: 2k21; Power_W: 63mW; Value2: 0.063W; VDC_V: 50V; TempCo: 100 ppm/C; EIA_Code: E96; AEC Category: Q200; AEC Grade: 0; AEC Qualified: Y; SizeArea_mm2: 0.5; SizeX_mm: 1; SizeZ_mm: 0.6
R3 = CMP-0026464-2: RES, 5.23 k, 1%, 0.063 W, AEC-Q200 Grade 0, 0402; PartNumber: CRCW04025K23FKED; Manufacturer: Vishay-Dale; Value_Code: 5k23; Power_W: 63mW; Value2: 0.063W; VDC_V: 50V; TempCo: 100 ppm/C; EIA_Code: E96; AEC Category: Q200; AEC Qualified: Y; AEC Grade: 0; SizeArea_mm2: 0.5; SizeX_mm: 1; SizeZ_mm: 0.6
R4 = CMP-0022788-4: RES, 137 k, 1%, 0.1 W, 0603; Manufacturer: Yageo; Power_W: 100mW; TempCo: 100 ppm/C; Value: 137k; EIA_Code: E96; SizeX_mm: 1.6; SizeY_mm: 0.8; SizeZ_mm: 1; Value2: 0.1W; SizeArea_mm2: 1.28; AEC Qualified: N; VDC_V: 75V; AEC Category: Q200; SizeAreaWB_mm2: 4.68
R5 = CMP-0026284-2: RES, 30.1 k, 1%, 0.063 W, AEC-Q200 Grade 0, 0402; PartNumber: CRCW040230K1FKED; Manufacturer: Vishay-Dale; Value_Code: 30k1; Power_W: 63mW; Value2: 0.063W; VDC_V: 50V; TempCo: 100 ppm/C; EIA_Code: E96; AEC Category: Q200; AEC Qualified: Y; AEC Grade: 0; SizeArea_mm2: 0.5; SizeX_mm: 1; SizeZ_mm: 0.6
R6 = CMP-0022735-5: RES, 100 k, 1%, 0.1 W, 0603; Manufacturer: Yageo; Power_W: 100mW; TempCo: 100 ppm/C; Value: 100k; EIA_Code: E96; SizeX_mm: 1.6; SizeY_mm: 0.8; SizeZ_mm: 1; Value2: 0.1W; SizeArea_mm2: 1.28; AEC Qualified: N; VDC_V: 75V; AEC Category: Q200; SizeAreaWB_mm2: 4.68
R7 = CMP-0025958-3: RES, 10.0 k, 1%, 0.063 W, AEC-Q200 Grade 0, 0402; PartNumber: CRCW040210K0FKED; Manufacturer: Vishay-Dale; Res_ohm: 10k; Value_Code: 10k0; Power_W: 63mW; Value2: 0.063W; VDC_V: 50V; TempCo: 100 ppm/C; EIA_Code: E96; AEC Category: Q200; AEC Qualified: Y; AEC Grade: 0; SizeArea_mm2: 0.5; SizeX_mm: 1; SizeZ_mm: 0.6
R8 = CMP-0023246-5: RES, 6.04 k, 1%, 0.1 W, 0603; Manufacturer: Yageo; Power_W: 100mW; TempCo: 100 ppm/C; Value_Code: 6k04; Value: 6.04k; EIA_Code: E96; SizeX_mm: 1.6; SizeY_mm: 0.8; SizeZ_mm: 1; Value2: 0.1W; SizeArea_mm2: 1.28; AEC Qualified: N; VDC_V: 75V; AEC Category: Q200; SizeAreaWB_mm2: 4.68
R9 = CMP-0022000-4: RES, 10.5 k, 1%, 0.1 W, AEC-Q200 Grade 0, 0603; Manufacturer: Vishay-Dale; Power_W: 100mW; TempCo: 100 ppm/C; Value_Code: 10k5; Value: 10.5k; EIA_Code: E96; SizeX_mm: 1.6; SizeY_mm: 0.8; SizeZ_mm: 1; Value2: 0.1W; SizeArea_mm2: 1.28; AEC Qualified: Y; VDC_V: 75V; AEC Category: Q200; AEC Grade: 0
R10 = CMP-0022089-4: RES, 17.4 k, 1%, 0.1 W, AEC-Q200 Grade 0, 0603; Manufacturer: Vishay-Dale; Power_W: 100mW; TempCo: 100 ppm/C; Value_Code: 17k4; Value: 17.4k; EIA_Code: E96; SizeX_mm: 1.6; SizeY_mm: 0.8; SizeZ_mm: 1; Value2: 0.1W; SizeArea_mm2: 1.28; AEC Qualified: Y; VDC_V: 75V; AEC Category: Q200; AEC Grade: 0
R11 = CMP-0017299-3: RES, 10.0, 1%, 0.25 W, AEC-Q200 Grade 0, 1206; Manufacturer: Panasonic; Power_W: 250mW; TempCo: 100 ppm/C; Value_Code: 10R0; Value: 10.0; EIA_Code: E96; Res_ohm: 10; SizeX_mm: 3.2; SizeY_mm: 1.6; SizeZ_mm: 1.35; Value2: 0.25W; SizeArea_mm2: 5.12; AEC Qualified: Y; VDC_V: 200V; AEC Category: Q200; AEC Grade: 0; SizeAreaWB_mm2: 10.92
R21 R22 = CMP-0027272-3: as R24 on sheet TPS25750D
TP1 = CMP-0055137-1: Test Point, Miniature, Red, TH; Manufacturer: Keystone; CNHeader: FALSE; ContactFinish: Silver; CT: TRUE; Green_Lifecycle: Active; Green_REACh: Passed
TP2 TP3 = CMP-0055153-1: Test Point, Compact, SMT; Manufacturer: Keystone; CNHeader: FALSE; CT: TRUE; Green_Lifecycle: Active; Green_REACh: Passed
U1 = CMP-0088656-1: BQ2579x HotRod; Manufacturer: Texas Instruments; SizeZ_mm: 1mm; Standoff Height: 0mm

## Sheet Type_C_Port.SchDoc
size A2; Date: Not shown in title block; ApprovedBy: Not shown in title block; CheckedBy: Not shown in title block; Author: Not shown in title block; CompanyName: Not shown in title block; Engineer: Not shown in title block; Organization: Not shown in title block; Address1: Not shown in title block; Address2: Not shown in title block; Address3: Not shown in title block; Address4: Not shown in title block; DocumentNumber: 2; Revision: Use project parameter SCH_Rev; SheetNumber: 2; SheetTotal: 3; PageSetup: Record=PageOptions¦CenterHorizontal=True¦CenterVertical=True¦PrintScale=1.00¦XCorrection=1.00¦YCorrection=1.00¦PrintKind=0¦BorderSize=5000000¦LeftOffset=0¦BottomOffset=0¦Orientation=2¦PaperLength=1000¦PaperWidth=1000¦Scale=100¦PaperSource=15¦PrintQuality=600¦MediaType=1¦DitherType=10¦PaperKind=Letter¦PrintScaleMode=1
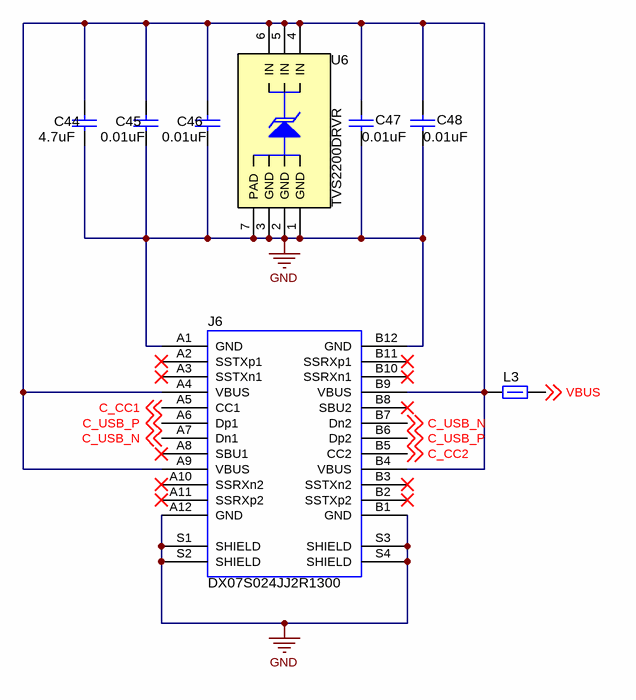
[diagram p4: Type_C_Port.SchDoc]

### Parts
C44  ValueDisplayed: 4.7uF  [0603]  (hidden comment: GRM188R6YA475KE15D)
C45  ValueDisplayed: 0.01uF  [0402]  (hidden comment: C0402C103J5RACTU)
C46  ValueDisplayed: 0.01uF  [0402]  (hidden comment: C0402C103J5RACTU)
C47  ValueDisplayed: 0.01uF  [0402]  (hidden comment: C0402C103J5RACTU)
C48  ValueDisplayed: 0.01uF  [0402]  (hidden comment: C0402C103J5RACTU)
J6  DX07S024JJ2R1300  [JAE_DX07S024JJ2R1300]
L3  FBMJ2125HM210NT  [0805_HV]  (value not drawn)
U6  TVS2200DRVR  [DRV0006A]

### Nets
GND: C44.2 C45.1 C46.1 C47.1 C48.1 J6.A1(GND) J6.A12(GND) J6.B1(GND) J6.B12(GND) J6.S1(SHIELD) J6.S2(SHIELD) J6.S3(SHIELD) J6.S4(SHIELD) U6.1(GND) U6.2(GND) U6.3(GND) U6.7(PAD)
C_CC1: J6.A5(CC1) ; off-sheet C_CC1
C_CC2: J6.B5(CC2) ; off-sheet C_CC2
C_USB_N: J6.A7(Dn1) J6.B7(Dn2) ; off-sheet C_USB_N
C_USB_P: J6.A6(Dp1) J6.B6(Dp2) ; off-sheet C_USB_P
VBUS: L3.2 ; off-sheet VBUS
NetC44_1: C44.1 C45.2 C46.2 C47.2 C48.2 J6.A4(VBUS) J6.A9(VBUS) J6.B4(VBUS) J6.B9(VBUS) L3.1 U6.4(IN) U6.5(IN) U6.6(IN)

Not connected (* = marked no-connect by the designer): J6 A2(SSTXp1)* A3(SSTXn1)* A8(SBU1)* A10(SSRXn2)* A11(SSRXp2)* B2(SSTXp2)* B3(SSTXn2)* B8(SBU2)* B10(SSRXn1)* B11(SSRXp1)*

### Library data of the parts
C44 = CMP-0007357-5: CAP, CERM, 4.7 uF, 35 V, +/- 10%, X5R, 0603; Manufacturer: MuRata; TaMin_C: -55°C; Polarized: N; SizeAreaWB_mm2: 4.68; Value1: Unknown; U/M: EA; Value: 4.7uF; TaMax_C: 85°C; SizeZ_mm: 1; SizeX_mm: 1.6; SizeY_mm: 0.8; Value2: 35V; SizeArea_mm2: 1.28; Cap_F: 4.7µF; AEC Category: Q200
C45-C48 = CMP-0006236-2: CAP, CERM, 0.01 uF, 50 V, +/- 5%, X7R, 0402; Manufacturer: Kemet; TaMin_C: -55°C; Polarized: N; SizeAreaWB_mm2: 3; Value1: Unknown; U/M: EA; Value: 0.01uF; TaMax_C: 125°C; SizeZ_mm: 0.6; SizeX_mm: 1; SizeY_mm: 0.5; Value2: 50V; Cap_F: 10nF; AEC Category: Q200
J6 = CMP-0085712-2: Receptacle, USB 3.1 Type C, R/A, Gold, SMT; Manufacturer: JAE Electronics; Current_A: 1.25A; Gender: Female; Voltage_V: 20V; Pitch_mm: 0.5; Row_Count: 2
L3 = CMP-0003375-1: Ferrite Bead, 21 ohm @ 100 MHz, 6 A, 0805; Manufacturer: Taiyo Yuden; ZTyp@100MHz_Ohm: 21; SizeAreaWB_mm2: 6.75; DCR_ohm: 4m; Value1: 0.004 ohm; Value: 21 ohm; Imax_A: 6A; SizeZ_mm: 1.45; SizeX_mm: 2; SizeY_mm: 1.25; SizeArea_mm2: 2.5
U6 = CMP-0077834-1: 22-V Precision Surge Protection Clamp, DRV0006A (WSON-6); Alternate Manufacturer: Texas Instruments; SizeAreaWB_mm2: 9.0; SizeZ_mm: 0.8; SizeX_mm: 2.0; SizeArea_mm2: 4.0; CompType: IC; AEC Qualified: N; AEC Category: Q200

## Sheet Power_5V_3.3V.SchDoc
size A2; Date: Not shown in title block; ApprovedBy: Not shown in title block; CheckedBy: Not shown in title block; Author: Not shown in title block; CompanyName: Not shown in title block; Engineer: Not shown in title block; Organization: Not shown in title block; Address1: Not shown in title block; Address2: Not shown in title block; Address3: Not shown in title block; Address4: Not shown in title block; DocumentNumber: 2; Revision: Use project parameter SCH_Rev; SheetNumber: 2; SheetTotal: 3; PageSetup: Record=PageOptions¦CenterHorizontal=True¦CenterVertical=True¦PrintScale=1.00¦XCorrection=1.00¦YCorrection=1.00¦PrintKind=0¦BorderSize=5000000¦LeftOffset=0¦BottomOffset=0¦Orientation=2¦PaperLength=1000¦PaperWidth=1000¦Scale=100¦PaperSource=15¦PrintQuality=600¦MediaType=1¦DitherType=10¦PaperKind=Letter¦PrintScaleMode=1
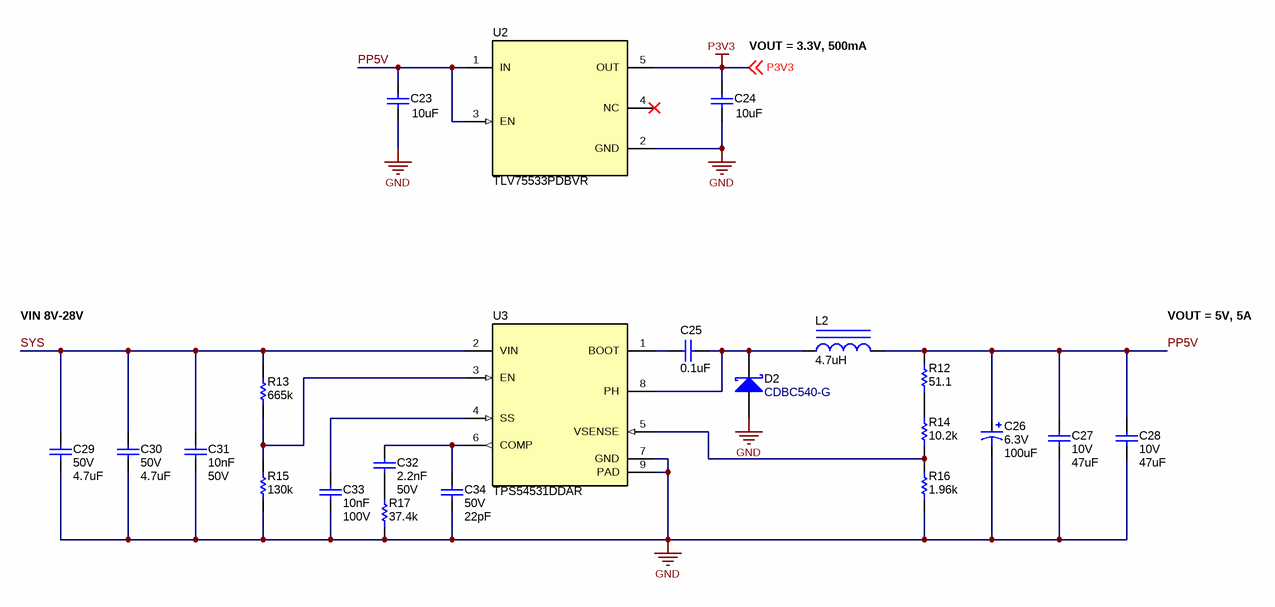
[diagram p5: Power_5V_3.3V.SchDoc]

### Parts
C23  ValueDisplayed: 10uF  [0603]  (hidden comment: GRT188R61E106ME13D)
C24  ValueDisplayed: 10uF  [0603]  (hidden comment: GRT188R61E106ME13D)
C25  ValueDisplayed: 0.1uF  [0402]  (hidden comment: C1005X7R1H104K050BE)
C26  VDC_V: 6.3V  ValueDisplayed: 100uF  [3528-21]  (hidden comment: T520B107M006ATE015)
C27  VDC_V: 10V  ValueDisplayed: 47uF  [1210_270]  (hidden comment: GRM32ER61A476KE20L)
C28  VDC_V: 10V  ValueDisplayed: 47uF  [1210_270]  (hidden comment: GRM32ER61A476KE20L)
C29  VDC_V: 50V  ValueDisplayed: 4.7uF  [1210_270]  (hidden comment: GRM32ER71H475KA88L)
C30  VDC_V: 50V  ValueDisplayed: 4.7uF  [1210_270]  (hidden comment: GRM32ER71H475KA88L)
C31  Cap_F: 10nF  VDC_V: 50V  [0805_HV]  (hidden comment: GRM216R71H103KA01D)
C32  Cap_F: 2.2nF  VDC_V: 50V  [0603]  (hidden comment: GRM188R71H222KA01D)
C33  Cap_F: 10nF  VDC_V: 100V  [0603]  (hidden comment: 06031C103KAT2A)
C34  VDC_V: 50V  ValueDisplayed: 22pF  [0603]  (hidden comment: GRM1885C1H220JA01D)
D2  CDBC540-G  [SMC]
L2  ValueDisplayed: 4.7uH  [WE-LHMI_1040]  (hidden comment: 74437368047)
R12  ValueDisplayed: 51.1  [0603]  (hidden comment: CRCW060351R1FKEA)
R13  ValueDisplayed: 665k  [0603]  (hidden comment: CRCW0603665KFKEA)
R14  ValueDisplayed: 10.2k  [0603]  (hidden comment: CRCW060310K2FKEA)
R15  ValueDisplayed: 130k  [0603]  (hidden comment: CRCW0603130KFKEA)
R16  ValueDisplayed: 1.96k  [0603]  (hidden comment: CRCW06031K96FKEA)
R17  ValueDisplayed: 37.4k  [0603]  (hidden comment: CRCW060337K4FKEA)
U2  TLV75533PDBVR  [DBV0005A_N]
U3  TPS54531DDAR  [DDA0008E_L]

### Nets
GND: C23.1 C24.1 C26.2(-) C27.2 C28.2 C29.2 C30.2 C31.2 C33.2 C34.2 D2.2(A) R15.1 R16.1 R17.1 U2.2(GND) U3.7(GND) U3.9(PAD)
P3V3: C24.2 U2.5(OUT) ; off-sheet P3V3
PP5V: C23.2 C26.1(+) C27.1 C28.1 L2.2 R12.2 U2.1(IN) U2.3(EN)
SYS: C29.1 C30.1 C31.1 R13.2 U3.2(VIN)
NetC25_1: C25.1 U3.1(BOOT)
NetC25_2: C25.2 D2.1(K) L2.1 U3.8(PH)
NetC32_1: C32.1 C34.1 U3.6(COMP)
NetC32_2: C32.2 R17.2
NetC33_1: C33.1 U3.4(SS)
NetR12_1: R12.1 R14.2
NetR13_1: R13.1 R15.2 U3.3(EN)
NetR14_1: R14.1 R16.2 U3.5(VSENSE)

Not connected (* = marked no-connect by the designer): U2 4(NC)*

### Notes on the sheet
- (near C24) VOUT = 3.3V, 500mA
- VIN 8V-28V
- VOUT = 5V, 5A

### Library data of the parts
C23 C24 = CMP-0007501-5: as C2 on sheet BQ25792
C25 = CMP-0064946-2: as C6 on sheet BQ25792
C26 = CMP-0011556-2: CAP, TA, 100 uF, 6.3 V, +/- 20%, 0.015 ohm, SMD; Manufacturer: Kemet; TaMin_C: -55°C; ESR_ohm: 0.015; Polarized: Y; SizeAreaWB_mm2: 17.1; U/M: EA; Value: 100uF; TaMax_C: 105°C; SizeZ_mm: 2.1; SizeX_mm: 3.5; SizeY_mm: 2.8; SizeArea_mm2: 9.8; CompType: Capacitor; AEC Qualified: N; Cap_F: 100µF; IRMS_A: 2.9A; AEC Category: Q200
C27 C28 = CMP-0009208-2: CAP, CERM, 47 uF, 10 V, +/- 10%, X5R, 1210; Manufacturer: MuRata; TaMin_C: -55°C; ESR_ohm: 1m; Polarized: N; SizeAreaWB_mm2: 14.7; Value1: 0.001 ohm; U/M: EA; Value: 47uF; TaMax_C: 85°C; SizeZ_mm: 2.7; SizeX_mm: 3.2; SizeY_mm: 2.5; Cap_Case: 1210; SizeArea_mm2: 8; Cap_F: 47µF; AEC Category: Q200
C29 C30 = CMP-0009228-2: CAP, CERM, 4.7 uF, 50 V, +/- 10%, X7R, 1210; Manufacturer: MuRata; TaMin_C: -55°C; ESR_ohm: 2m; Polarized: N; SizeAreaWB_mm2: 14.7; Value1: 0.002 ohm; U/M: EA; Value: 4.7uF; TaMax_C: 125°C; SizeZ_mm: 2.7; SizeX_mm: 3.2; SizeY_mm: 2.5; Cap_Case: 1210; SizeArea_mm2: 8; Cap_F: 4.7µF; AEC Category: Q200
C31 = CMP-0008154-2: CAP, CERM, 0.01 uF, 50 V, +/- 10%, X7R, 0805; Manufacturer: MuRata; TaMin_C: -55°C; Polarized: N; SizeAreaWB_mm2: 6.75; Value1: Unknown; U/M: EA; Value: 0.01uF; TaMax_C: 125°C; SizeZ_mm: 1.45; SizeX_mm: 2; SizeY_mm: 1.25; Cap_Case: 0805; SizeArea_mm2: 2.5; AEC Category: Q200
C32 = CMP-0007443-4: CAP, CERM, 2200 pF, 50 V, +/- 10%, X7R, 0603; Manufacturer: MuRata; TaMin_C: -55°C; Polarized: N; SizeAreaWB_mm2: 4.68; Value1: Unknown; U/M: EA; Value: 2200pF; TaMax_C: 125°C; SizeZ_mm: 1; SizeX_mm: 1.6; SizeY_mm: 0.8; SizeArea_mm2: 1.28; AEC Category: Q200
C33 = CMP-0006727-4: CAP, CERM, 0.01 uF, 100 V, +/- 10%, X7R, 0603; Manufacturer: AVX; TaMin_C: -55°C; ESR_ohm: 0.098; Polarized: N; SizeAreaWB_mm2: 4.68; Value1: 0.098 ohm; U/M: EA; Value: 0.01uF; TaMax_C: 125°C; SizeZ_mm: 1; SizeX_mm: 1.6; SizeY_mm: 0.8; SizeArea_mm2: 1.28; AEC Category: Q200
C34 = CMP-0007196-4: CAP, CERM, 22 pF, 50 V, +/- 5%, C0G/NP0, 0603; Manufacturer: MuRata; TaMin_C: -55°C; Polarized: N; SizeAreaWB_mm2: 4.68; Value1: Unknown; U/M: EA; Value: 22pF; TaMax_C: 125°C; SizeZ_mm: 1; SizeX_mm: 1.6; SizeY_mm: 0.8; SizeArea_mm2: 1.28; AEC Category: Q200
D2 = CMP-0028510-2: Diode, Schottky, 40 V, 5 A, SMC; Manufacturer: Comchip Technology; SizeZ_mm: 2.6; SizeAreaWB_mm2: 83.2686; Green_REACh: Incomplete; Green_Lifecycle: Not Set; Value1: 5A; Vf_V: 550mV; SizeY_mm: 6.22; Value2: 0.55V; AEC Category: Q101; SizeX_mm: 8.13; SizeArea_mm2: 50.5686; Value: 40V; TJmax_C: 125°C
L2 = CMP-0064124-1: Inductor, Shielded Drum Core, Powdered Iron, 4.7 uH, 7 A, 0.015 ohm, SMD; Manufacturer: Wurth Elektronik; Isat: 19A @ 20% inductance drop; Irms: 7A @ 40C rise; Green_Lifecycle: Active; SizeAreaWB_mm2: 156; DCR_ohm: 0.015; Green_REACh: Passed; Value: 4.7uH; Imax_A: 7A; SizeZ_mm: 4; SizeX_mm: 11; SizeY_mm: 10; SizeArea_mm2: 110; Ind_H: 4.7µH; AEC Category: Q200
R12 = CMP-0022483-4: RES, 51.1, 1%, 0.1 W, AEC-Q200 Grade 0, 0603; Manufacturer: Vishay-Dale; Power_W: 100mW; TempCo: 100 ppm/C; Value_Code: 51R1; Value: 51.1; EIA_Code: E96; SizeX_mm: 1.6; SizeY_mm: 0.8; SizeZ_mm: 1; Value2: 0.1W; SizeArea_mm2: 1.28; AEC Qualified: Y; VDC_V: 75V; AEC Category: Q200; AEC Grade: 0
R13 = CMP-0022546-4: RES, 665 k, 1%, 0.1 W, AEC-Q200 Grade 0, 0603; Manufacturer: Vishay-Dale; Power_W: 100mW; TempCo: 100 ppm/C; Value: 665k; EIA_Code: E96; SizeX_mm: 1.6; SizeY_mm: 0.8; SizeZ_mm: 1; Value2: 0.1W; SizeArea_mm2: 1.28; AEC Qualified: Y; VDC_V: 75V; AEC Category: Q200; AEC Grade: 0
R14 = CMP-0021999-4: RES, 10.2 k, 1%, 0.1 W, AEC-Q200 Grade 0, 0603; Manufacturer: Vishay-Dale; Power_W: 100mW; TempCo: 100 ppm/C; Value_Code: 10k2; Value: 10.2k; EIA_Code: E96; SizeX_mm: 1.6; SizeY_mm: 0.8; SizeZ_mm: 1; Value2: 0.1W; SizeArea_mm2: 1.28; AEC Qualified: Y; VDC_V: 75V; AEC Category: Q200; AEC Grade: 0
R15 = CMP-0022036-4: RES, 130 k, 1%, 0.1 W, AEC-Q200 Grade 0, 0603; Manufacturer: Vishay-Dale; Power_W: 100mW; TempCo: 100 ppm/C; Value: 130k; EIA_Code: E96; SizeX_mm: 1.6; SizeY_mm: 0.8; SizeZ_mm: 1; Value2: 0.1W; SizeArea_mm2: 1.28; AEC Qualified: Y; VDC_V: 75V; AEC Category: Q200; AEC Grade: 0
R16 = CMP-0022137-4: RES, 1.96 k, 1%, 0.1 W, AEC-Q200 Grade 0, 0603; Manufacturer: Vishay-Dale; Power_W: 100mW; TempCo: 100 ppm/C; Value_Code: 1k96; Value: 1.96k; EIA_Code: E96; SizeX_mm: 1.6; SizeY_mm: 0.8; SizeZ_mm: 1; Value2: 0.1W; SizeArea_mm2: 1.28; AEC Qualified: Y; VDC_V: 75V; AEC Category: Q200; AEC Grade: 0
R17 = CMP-0022360-4: RES, 37.4 k, 1%, 0.1 W, AEC-Q200 Grade 0, 0603; Manufacturer: Vishay-Dale; Power_W: 100mW; TempCo: 100 ppm/C; Value_Code: 37k4; Value: 37.4k; EIA_Code: E96; SizeX_mm: 1.6; SizeY_mm: 0.8; SizeZ_mm: 1; Value2: 0.1W; SizeArea_mm2: 1.28; AEC Qualified: Y; VDC_V: 75V; AEC Category: Q200; AEC Grade: 0
U2 = CMP-0074640-3: 500-mA, Low IQ, Small Size, Low Dropout Regulator, DBV0005A (SOT-23-5); Manufacturer: Texas Instruments; SizeX_mm: 2.8; SizeY_mm: 2.9; CompType: IC; SizeZ_mm: 1.45; SizeArea_mm2: 8.12; SizeAreaWB_mm2: 14.82; AEC Category: Q200; AEC Qualified: N
U3 = CMP-0067056-2: 3.5V to 28V Input, 5A, 570kHz Step-Down Converter with Eco-mode, DDA0008E (SOIC-8); Alternate Manufacturer: Texas Instruments; Green_Lifecycle: Active; SizeAreaWB_mm2: 57.4; Green_REACh: Passed; U/M: EA; SizeZ_mm: 1.7; SizeX_mm: 5.0; SizeY_mm: 6.2; SizeArea_mm2: 31.0; CompType: IC

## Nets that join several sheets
GND: TPS25750D (23 pins), BQ25792 (25 pins), Type_C_Port (17 pins), Power_5V_3.3V (17 pins)
P3V3: TPS25750D (C35.1 U4.38), BQ25792 (R11.2), Power_5V_3.3V (C24.2 U2.5)
C_CC1: TPS25750D (C42.1 U4.28), Type_C_Port (J6.A5)
C_CC2: TPS25750D (C41.1 U4.29), Type_C_Port (J6.B5)
C_USB_N: TPS25750D (U4.27), Type_C_Port (J6.A7 J6.B7)
C_USB_P: TPS25750D (U4.26), Type_C_Port (J6.A6 J6.B6)
I2C1_SCL: TPS25750D (U4.9), BQ25792 (J3.9 R21.1)
I2C1_SDA: TPS25750D (U4.8), BQ25792 (J3.10 R22.1)
I2C_SCL: TPS25750D (5 pins), BQ25792 (U1.14)
I2C_SDA: TPS25750D (5 pins), BQ25792 (U1.15)
LDO_3V3: TPS25750D (6 pins), BQ25792 (R2.2 R21.2 R22.2)
PP5V: TPS25750D (U4.34 U4.35), Power_5V_3.3V (8 pins)
PPHV: TPS25750D (6 pins), BQ25792 (10 pins)
SYS: BQ25792 (8 pins), Power_5V_3.3V (5 pins)
VBUS: TPS25750D (5 pins), Type_C_Port (L3.2)

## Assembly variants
001: not fitted C2 C3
